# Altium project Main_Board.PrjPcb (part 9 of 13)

## Sheet Ext_GPIO_Bank2.SchDoc
size A3
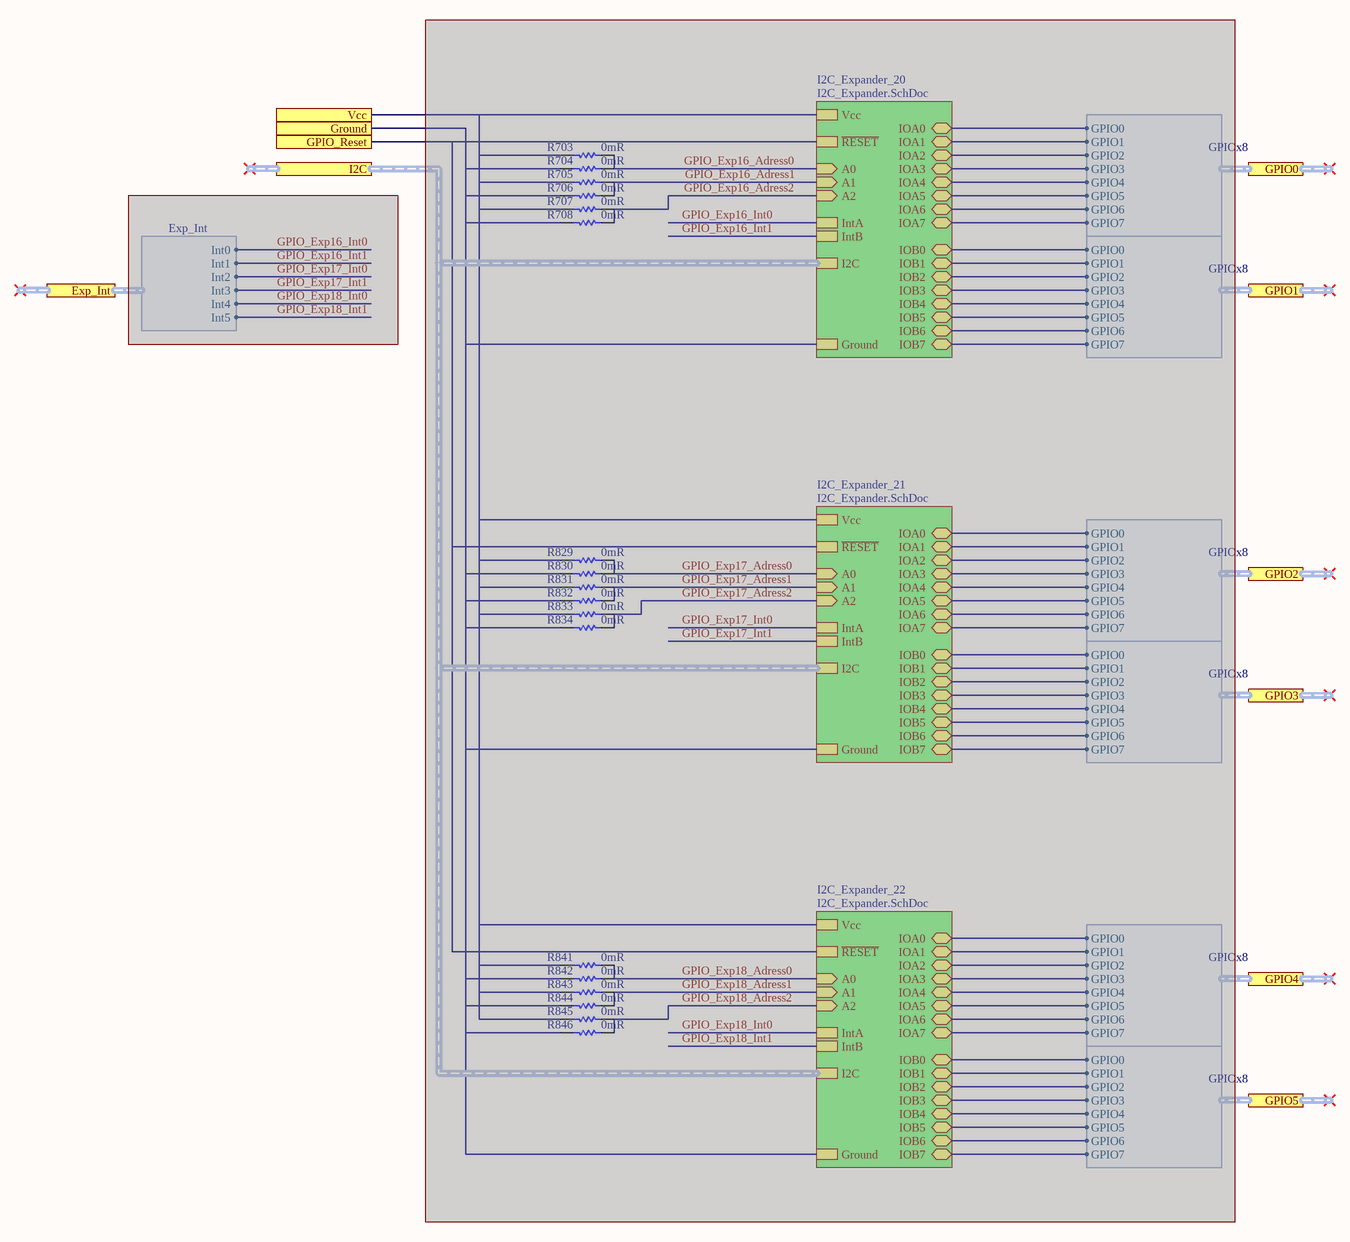
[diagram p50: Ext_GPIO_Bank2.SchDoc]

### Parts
(Parts that share a designator on the sheet are numbered #1, #2 ... from top to bottom, then left to right.)
R703#1  0mR  [RES 0402/1005 RF KK]  (masked out: inside a compile mask, not in the netlist)
R704#1  0mR  [RES 0402/1005 RF KK]  (masked out: inside a compile mask, not in the netlist)
R705#1  0mR  [RES 0402/1005 RF KK]  (masked out: inside a compile mask, not in the netlist)
R706#1  0mR  [RES 0402/1005 RF KK]  (masked out: inside a compile mask, not in the netlist)
R707#1  0mR  [RES 0402/1005 RF KK]  (masked out: inside a compile mask, not in the netlist)
R708#1  0mR  [RES 0402/1005 RF KK]  (masked out: inside a compile mask, not in the netlist)
R829#1  0mR  [RES 0402/1005 RF KK]  (masked out: inside a compile mask, not in the netlist)
R830#1  0mR  [RES 0402/1005 RF KK]  (masked out: inside a compile mask, not in the netlist)
R831#1  0mR  [RES 0402/1005 RF KK]  (masked out: inside a compile mask, not in the netlist)
R832#1  0mR  [RES 0402/1005 RF KK]  (masked out: inside a compile mask, not in the netlist)
R833#1  0mR  [RES 0402/1005 RF KK]  (masked out: inside a compile mask, not in the netlist)
R834#1  0mR  [RES 0402/1005 RF KK]  (masked out: inside a compile mask, not in the netlist)
R841#1  0mR  [RES 0402/1005 RF KK]  (masked out: inside a compile mask, not in the netlist)
R842#1  0mR  [RES 0402/1005 RF KK]  (masked out: inside a compile mask, not in the netlist)
R843#1  0mR  [RES 0402/1005 RF KK]  (masked out: inside a compile mask, not in the netlist)
R844#1  0mR  [RES 0402/1005 RF KK]  (masked out: inside a compile mask, not in the netlist)
R845#1  0mR  [RES 0402/1005 RF KK]  (masked out: inside a compile mask, not in the netlist)
R846#2  0mR  [RES 0402/1005 RF KK]  (masked out: inside a compile mask, not in the netlist)

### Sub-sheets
I2C_Expander_20 = I2C_Expander.SchDoc (masked out): IOA7 (bidir), IOA3 (bidir), IOA6 (bidir), IOA1 (bidir), IOA0 (bidir), IOA5 (bidir), IOB1 (bidir), IOB2 (bidir), IOB5 (bidir), IOB6 (bidir), IOB7 (bidir), IntA, IntB, Ground, IOB4 (bidir), IOB3 (bidir), IOA2 (bidir), IOA4 (bidir), IOB0 (bidir), Vcc, ~{RESET}, I2C (harness I2C), A2 (in), A1 (in), A0 (in)
I2C_Expander_21 = I2C_Expander.SchDoc (masked out): IOA7 (bidir), IOA3 (bidir), IOA6 (bidir), IOA1 (bidir), IOA0 (bidir), IOA5 (bidir), IOB1 (bidir), IOB2 (bidir), IOB5 (bidir), IOB6 (bidir), IOB7 (bidir), IntA, IntB, Ground, IOB4 (bidir), IOB3 (bidir), IOA2 (bidir), IOA4 (bidir), IOB0 (bidir), Vcc, ~{RESET}, I2C (harness I2C), A2 (in), A1 (in), A0 (in)
I2C_Expander_22 = I2C_Expander.SchDoc (masked out): IOA7 (bidir), IOA3 (bidir), IOA6 (bidir), IOA1 (bidir), IOA0 (bidir), IOA5 (bidir), IOB1 (bidir), IOB2 (bidir), IOB5 (bidir), IOB6 (bidir), IOB7 (bidir), IntA, IntB, Ground, IOB4 (bidir), IOB3 (bidir), IOA2 (bidir), IOA4 (bidir), IOB0 (bidir), Vcc, ~{RESET}, I2C (harness I2C), A2 (in), A1 (in), A0 (in)

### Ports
Exp_Int (harness Exp_Int), GPIO0 (harness GPIOx8), GPIO1 (harness GPIOx8), GPIO2 (harness GPIOx8), GPIO3 (harness GPIOx8), GPIO4 (harness GPIOx8), GPIO5 (harness GPIOx8), GPIO_Reset, Ground, I2C (harness I2C), Vcc

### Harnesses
GPIOx8: GPIO0, GPIO1, GPIO2, GPIO3, GPIO4, GPIO5, GPIO6, GPIO7
Exp_Int: Int0, Int1, Int2, Int3, Int4, Int5

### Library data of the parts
R703#1 R704#1 R705#1 R706#1 R707#1 R708#1 R829#1 R830#1 R831#1 R832#1 R833#1 R834#1 R841#1 R842#1 R843#1 R844#1 R845#1 R846#2 = Resistor: Manufacturer 1: Yageo; Manufacturer Part Number 1: RC0402JR-070RL; Power Rating: 62.5mW; Tolerance: 5%; Voltage Rating: 50V; Max Power Dissipation: 63mW; Temperature Coefficient: 200ppm/°C

## Sheet SFP_Group.SchDoc: SFP_Group
size A3
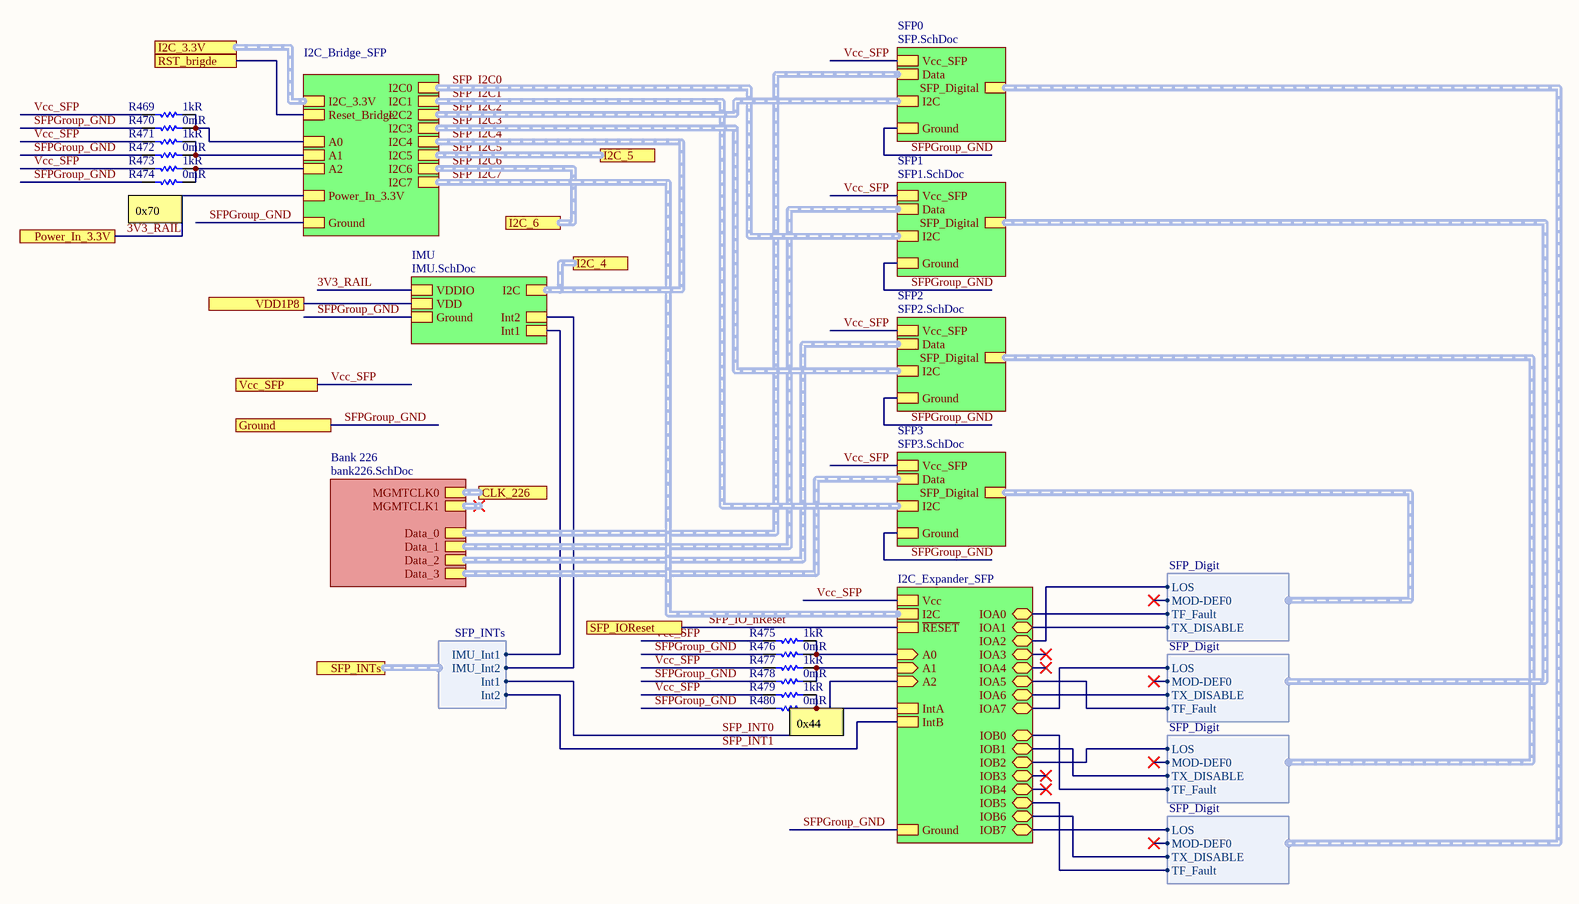
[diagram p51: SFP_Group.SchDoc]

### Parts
R469  1kR  [RES 0402/1005 RF KK]
R470  0mR  [RES 0402/1005 RF KK]
R471  1kR  [RES 0402/1005 RF KK]
R472  0mR  [RES 0402/1005 RF KK]
R473  1kR  [RES 0402/1005 RF KK]
R474  0mR  [RES 0402/1005 RF KK]
R475  1kR  [RES 0402/1005 RF KK]
R476  0mR  [RES 0402/1005 RF KK]
R477  1kR  [RES 0402/1005 RF KK]
R478  0mR  [RES 0402/1005 RF KK]
R479  1kR  [RES 0402/1005 RF KK]
R480  0mR  [RES 0402/1005 RF KK]

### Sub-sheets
Bank 226 = bank226.SchDoc: MGMTCLK0 (harness Diff_1Pair), MGMTCLK1 (harness Diff_1Pair), Data_3 (harness Diff_2PairData), Data_2 (harness Diff_2PairData), Data_1 (harness Diff_2PairData), Data_0 (harness Diff_2PairData)
I2C_Bridge_SFP = I2C_Bridge.SchDoc: I2C0 (harness I2C), I2C1 (harness I2C), I2C2 (harness I2C), I2C3 (harness I2C), I2C4 (harness I2C), I2C5 (harness I2C), I2C6 (harness I2C), I2C7 (harness I2C), A2, A1, A0, Ground, I2C_3.3V (harness I2C), Reset_Bridge, Power_In_3.3V
I2C_Expander_SFP = I2C_Expander.SchDoc: IOA7 (bidir), IOA3 (bidir), IOA6 (bidir), IOA1 (bidir), IOA0 (bidir), IOA5 (bidir), IOB1 (bidir), IOB2 (bidir), IOB5 (bidir), IOB6 (bidir), IOB7 (bidir), IntA, IntB, Ground, IOB4 (bidir), IOB3 (bidir), IOA2 (bidir), IOA4 (bidir), IOB0 (bidir), Vcc, ~{RESET}, I2C (harness I2C), A2 (in), A1 (in), A0 (in)
IMU = IMU.SchDoc: Ground, I2C (harness I2C), VDDIO, VDD, Int1, Int2
SFP0 = SFP.SchDoc: I2C (harness I2C), Vcc_SFP, SFP_Digital (harness SFP_Digit), Data (harness Diff_2PairData), Ground
SFP1 = SFP1.SchDoc: I2C (harness I2C), Vcc_SFP, SFP_Digital (harness SFP_Digit), Data (harness Diff_2PairData), Ground
SFP2 = SFP2.SchDoc: I2C (harness I2C), Vcc_SFP, SFP_Digital (harness SFP_Digit), Data (harness Diff_2PairData), Ground
SFP3 = SFP3.SchDoc: I2C (harness I2C), Vcc_SFP, SFP_Digital (harness SFP_Digit), Data (harness Diff_2PairData), Ground

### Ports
CLK_226 (harness Diff_1Pair), Ground, I2C_3.3V (harness I2C), I2C_4 (harness I2C), I2C_5 (harness I2C), I2C_6 (harness I2C), Power_In_3.3V, RST_brigde, SFP_INTs (harness SFP_INTs), SFP_IOReset, Vcc_SFP, VDD1P8

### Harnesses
SFP_Digit: LOS, MOD-DEF0, TF_Fault, TX_DISABLE
SFP_INTs: IMU_Int1, Int1, Int2, IMU_Int2

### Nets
SFPGroup_GND: R470.2 R472.2 R474.2 R476.2 R478.2 R480.2 ; port Ground, sheet SFP0/Ground, sheet SFP1/Ground, sheet SFP2/Ground, sheet SFP3/Ground, sheet I2C_Bridge_SFP/Ground, sheet IMU/Ground, sheet I2C_Expander_SFP/Ground  [project net B503_Ground]
1V8@1.5A: port VDD1P8, sheet IMU/VDD
3V3_RAIL: R469.1 R471.1 R473.1 R475.1 R477.1 R479.1 ; port Vcc_SFP, port Power_In_3.3V, sheet SFP0/Vcc_SFP, sheet SFP1/Vcc_SFP, sheet SFP2/Vcc_SFP, sheet SFP3/Vcc_SFP, sheet I2C_Bridge_SFP/Power_In_3.3V, sheet IMU/VDDIO, sheet I2C_Expander_SFP/Vcc  [also labelled Vcc_SFP]
IMU_INT1: sheet IMU/Int1, port SFP_INTs.IMU_Int1
IMU_INT2: sheet IMU/Int2, port SFP_INTs.IMU_Int2
RST_brigde: port RST_brigde, sheet I2C_Bridge_SFP/Reset_Bridge
SFP0_LOS: sheet I2C_Expander_SFP/IOB7, sheet SFP0/SFP_Digital.LOS
SFP0_TxDis: sheet I2C_Expander_SFP/IOB6, sheet SFP0/SFP_Digital.TX_DISABLE
SFP0_TxF: sheet I2C_Expander_SFP/IOB5, sheet SFP0/SFP_Digital.TF_Fault
SFP1_LOS: sheet I2C_Expander_SFP/IOA7, sheet SFP1/SFP_Digital.LOS
SFP1_TxDis: sheet I2C_Expander_SFP/IOA6, sheet SFP1/SFP_Digital.TX_DISABLE
SFP1_TxF: sheet I2C_Expander_SFP/IOA5, sheet SFP1/SFP_Digital.TF_Fault
SFP2_LOS: sheet I2C_Expander_SFP/IOB2, sheet SFP2/SFP_Digital.LOS
SFP2_TxDis: sheet I2C_Expander_SFP/IOB1, sheet SFP2/SFP_Digital.TX_DISABLE
SFP2_TxF: sheet I2C_Expander_SFP/IOB0, sheet SFP2/SFP_Digital.TF_Fault
SFP3_LOS: sheet I2C_Expander_SFP/IOA2, sheet SFP3/SFP_Digital.LOS
SFP3_TxDis: sheet I2C_Expander_SFP/IOA1, sheet SFP3/SFP_Digital.TX_DISABLE
SFP3_TxF: sheet I2C_Expander_SFP/IOA0, sheet SFP3/SFP_Digital.TF_Fault
SFP_INT0: sheet I2C_Expander_SFP/IntA, port SFP_INTs.Int1
SFP_INT1: sheet I2C_Expander_SFP/IntB, port SFP_INTs.Int2
SFP_IO_nReset: port SFP_IOReset, sheet I2C_Expander_SFP/~{RESET}
NetR469_2: R469.2 R470.1 ; sheet I2C_Bridge_SFP/A0
NetR471_2: R471.2 R472.1 ; sheet I2C_Bridge_SFP/A1
NetR473_2: R473.2 R474.1 ; sheet I2C_Bridge_SFP/A2
NetR475_2: R475.2 R476.1 ; sheet I2C_Expander_SFP/A0
NetR477_2: R477.2 R478.1 ; sheet I2C_Expander_SFP/A1
NetR479_2: R479.2 R480.1 ; sheet I2C_Expander_SFP/A2

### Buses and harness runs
harness port CLK_226 = sheet Bank 226/MGMTCLK0
harness port I2C_3.3V = sheet I2C_Bridge_SFP/I2C_3.3V
harness SFP_I2C0 = sheet I2C_Bridge_SFP/I2C0 = sheet SFP1/I2C
harness SFP_I2C1 = sheet I2C_Bridge_SFP/I2C1 = sheet SFP3/I2C
harness SFP_I2C2 = sheet I2C_Bridge_SFP/I2C2 = sheet SFP0/I2C
harness SFP_I2C3 = sheet I2C_Bridge_SFP/I2C3 = sheet SFP2/I2C
harness SFP_I2C4 = port I2C_4 = sheet I2C_Bridge_SFP/I2C4 = sheet IMU/I2C
harness SFP_I2C5 = port I2C_5 = sheet I2C_Bridge_SFP/I2C5
harness SFP_I2C6 = port I2C_6 = sheet I2C_Bridge_SFP/I2C6
harness SFP_I2C7 = sheet I2C_Bridge_SFP/I2C7 = sheet I2C_Expander_SFP/I2C
harness sheet Bank 226/Data_0 = sheet SFP0/Data
harness sheet Bank 226/Data_1 = sheet SFP1/Data
harness sheet Bank 226/Data_2 = sheet SFP2/Data
harness sheet Bank 226/Data_3 = sheet SFP3/Data

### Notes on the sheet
- (near R474) 0x70
- (near R480) 0x44

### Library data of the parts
R469 R471 R473 R475 R477 R479 = Resistor: PANASONIC - ERJ-2RKF1001X - SMD Chip Resistor, 0402 [1005 Metric], 1 kohm, ERJ2R Series, 50 V, Thick Film, 100 mW; Temperature Coefficient: 100ppm/°C; Tolerance: 1%; Voltage Rating (DC): 50V; Power Rating: 100mW
R470 R472 R474 R476 R478 R480 = Resistor: as R703#1 on sheet Ext_GPIO_Bank2

## Sheet SFP.SchDoc: SFP
size A3; Organization: Altium Limited; Address1: L3, 12a Rodborough Rd; Address2: Frenchs Forest; Address3: NSW; Address4: Australia 2086
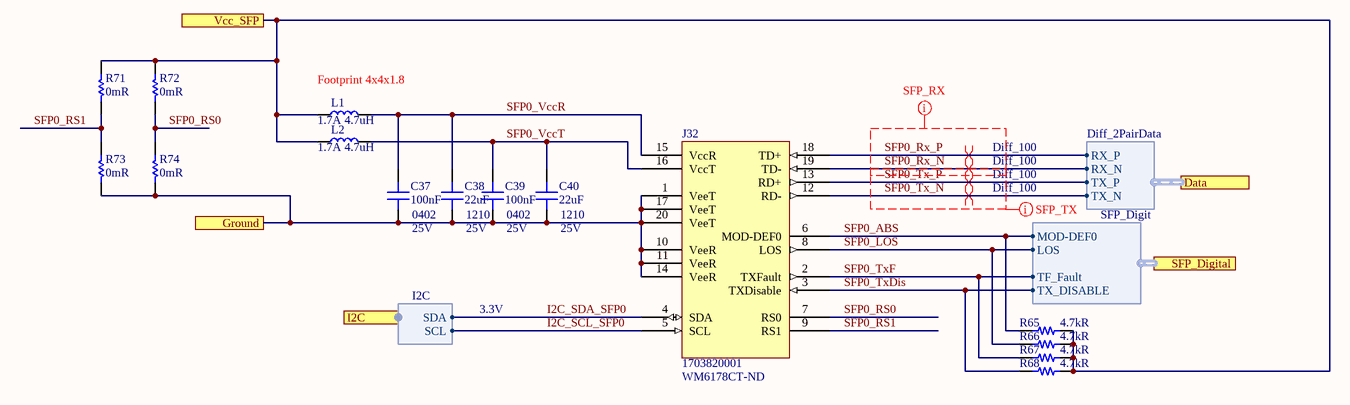
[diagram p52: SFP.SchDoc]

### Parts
C37  100nF  Case/Package: 0402  Voltage Rating: 25V  [CAP 0402/1005 KK]
C38  22uF  Case/Package: 1210  Voltage Rating: 25V  [CAP 1210/3225 - 1MM]
C39  100nF  Case/Package: 0402  Voltage Rating: 25V  [CAP 0402/1005 KK]
C40  22uF  Case/Package: 1210  Voltage Rating: 25V  [CAP 1210/3225 - 1MM]
J32  1703820001  Supplier Part Number 1: WM6178CT-ND  [1703820001]
L1  Inductance: 4.7uH  Current Rating: 1.7A  [NRS8040]  (hidden comment: NRS4018T4R7MDGJV)
L2  Inductance: 4.7uH  Current Rating: 1.7A  [NRS8040]  (hidden comment: NRS4018T4R7MDGJV)
R65  4.7kR  [RES 0402/1005 RF KK]
R66  4.7kR  [RES 0402/1005 RF KK]
R67  4.7kR  [RES 0402/1005 RF KK]
R68  4.7kR  [RES 0402/1005 RF KK]
R71  0mR  [RES 0402/1005 RF KK]
R72  0mR  [RES 0402/1005 RF KK]
R73  0mR  [RES 0402/1005 RF KK]
R74  0mR  [RES 0402/1005 RF KK]

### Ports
Data (harness Diff_2PairData), Ground, I2C (harness I2C), SFP_Digital (harness SFP_Digit), Vcc_SFP

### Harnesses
I2C: SDA, SCL
SFP_Digit: MOD-DEF0, LOS, TF_Fault, TX_DISABLE
Diff_2PairData: RX_P, RX_N, TX_P, TX_N

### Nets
B503_Ground: C37.1 C38.2 C39.1 C40.2 J32.1(VeeT) J32.10(VeeR) J32.11(VeeR) J32.14(VeeR) J32.17(VeeT) J32.20(VeeT) R73.2 R74.2 ; port Ground
3V3_RAIL: L1.1 L2.1 R65.2 R66.2 R67.2 R68.2 R71.1 R72.1 ; port Vcc_SFP
I2C_SCL_SFP0: J32.5(SCL) ; port I2C.SCL
I2C_SDA_SFP0: J32.4(SDA) ; port I2C.SDA
SFP0_ABS: J32.6(MOD-DEF0) R65.1 ; port SFP_Digital.MOD-DEF0
SFP0_LOS: J32.8(LOS) R66.1 ; port SFP_Digital.LOS
SFP0_RS0: J32.7(RS0) R72.2 R74.1
SFP0_RS1: J32.9(RS1) R71.2 R73.1
SFP0_Rx_N: J32.19(TD-) ; port Data.RX_N
SFP0_Rx_P: J32.18(TD+) ; port Data.RX_P
SFP0_Tx_N: J32.12(RD-) ; port Data.TX_N
SFP0_Tx_P: J32.13(RD+) ; port Data.TX_P
SFP0_TxDis: J32.3(TXDisable) R68.1 ; port SFP_Digital.TX_DISABLE
SFP0_TxF: J32.2(TXFault) R67.1 ; port SFP_Digital.TF_Fault
SFP0_VccR: C37.2 C38.1 J32.15(VccR) L1.2
SFP0_VccT: C39.2 C40.1 J32.16(VccT) L2.2

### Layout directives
differential pair; differential pair class Diff_100: SFP0_Rx_N, SFP0_Rx_P, SFP0_Tx_N, SFP0_Tx_P
net class SFP_RX: SFP0_Rx_N, SFP0_Rx_P
net class SFP_TX: SFP0_Rx_N, SFP0_Tx_N, SFP0_Tx_P

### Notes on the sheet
- (near L1) Footprint 4x4x1.8
- 3.3V

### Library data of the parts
C37 C39 = Capacitor: Manufacturer: Murata; Manufacturer Part Number: GRM155R71E104KE14J; Tolerance: 10%; Dielectric: X7R
C38 C40 = Capacitor: Manufacturer: Samsung; Manufacturer Part Number: CL32A226KAJNNNE; Material: Ceramic; Tolerance: 10%; Dielectric: X5R
J32 = 1703820001: Conn zSFP+ F 20 POS 0.8mm Solder RA SMD 20 Terminal 1 Port zSFP+™ Reel; Manufacturer: Molex; Number of Circuits: 20; Connector Type: Receptacle; Number of Ports: 1; Max Voltage Rating (AC): 120V; Gender: Female; Current Rating: 500mA
L1 L2 = NRS4018T4R7MDGJV: Ind Power Shielded Wirewound 4.7uH 20% 100KHz Ferrite 1.7A Embossed T/R; Manufacturer: Taiyo Yuden; Saturation Current: 2A; DC Resistance (DCR): 84mR; Self Resonant Frequency: 35MHz
R65-R68 = Resistor: Manufacturer: Panasonic; Manufacturer Part Number: ERJ-2RKF4701X; Tolerance: 1%; Temperature Coefficient: 100ppm/°C; Power Rating: 100mW; Voltage Rating: 50V
R71-R74 = Resistor: as R703#1 on sheet Ext_GPIO_Bank2

## Sheet SFP1.SchDoc: SFP1
size A3; Organization: Altium Limited; Address1: L3, 12a Rodborough Rd; Address2: Frenchs Forest; Address3: NSW; Address4: Australia 2086
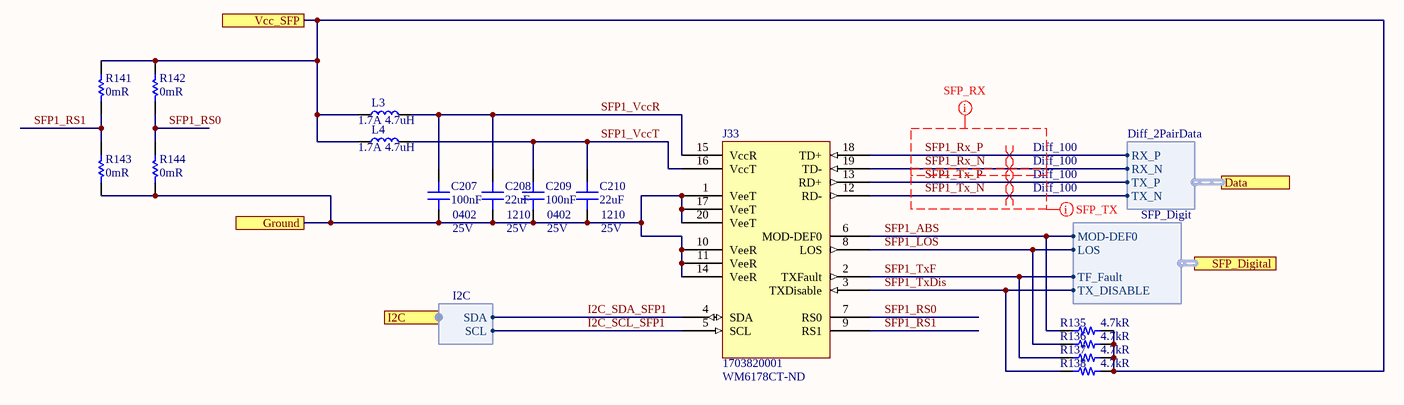
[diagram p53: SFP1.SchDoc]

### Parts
C207  100nF  Case/Package: 0402  Voltage Rating: 25V  [CAP 0402/1005 KK]
C208  22uF  Case/Package: 1210  Voltage Rating: 25V  [CAP 1210/3225 - 1MM]
C209  100nF  Case/Package: 0402  Voltage Rating: 25V  [CAP 0402/1005 KK]
C210  22uF  Case/Package: 1210  Voltage Rating: 25V  [CAP 1210/3225 - 1MM]
J33  1703820001  Supplier Part Number 1: WM6178CT-ND  [1703820001]
L3  Inductance: 4.7uH  Current Rating: 1.7A  [NRS8040]  (hidden comment: NRS4018T4R7MDGJV)
L4  Inductance: 4.7uH  Current Rating: 1.7A  [NRS8040]  (hidden comment: NRS4018T4R7MDGJV)
R135  4.7kR  [RES 0402/1005 RF KK]
R136  4.7kR  [RES 0402/1005 RF KK]
R137  4.7kR  [RES 0402/1005 RF KK]
R138  4.7kR  [RES 0402/1005 RF KK]
R141  0mR  [RES 0402/1005 RF KK]
R142  0mR  [RES 0402/1005 RF KK]
R143  0mR  [RES 0402/1005 RF KK]
R144  0mR  [RES 0402/1005 RF KK]

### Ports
Data (harness Diff_2PairData), Ground, I2C (harness I2C), SFP_Digital (harness SFP_Digit), Vcc_SFP

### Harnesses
I2C: SDA, SCL
SFP_Digit: MOD-DEF0, LOS, TF_Fault, TX_DISABLE
Diff_2PairData: RX_P, RX_N, TX_P, TX_N

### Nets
B503_Ground: C207.1 C208.2 C209.1 C210.2 J33.1(VeeT) J33.10(VeeR) J33.11(VeeR) J33.14(VeeR) J33.17(VeeT) J33.20(VeeT) R143.2 R144.2 ; port Ground
3V3_RAIL: L3.1 L4.1 R135.2 R136.2 R137.2 R138.2 R141.1 R142.1 ; port Vcc_SFP
I2C_SCL_SFP1: J33.5(SCL) ; port I2C.SCL
I2C_SDA_SFP1: J33.4(SDA) ; port I2C.SDA
SFP1_ABS: J33.6(MOD-DEF0) R135.1 ; port SFP_Digital.MOD-DEF0
SFP1_LOS: J33.8(LOS) R136.1 ; port SFP_Digital.LOS
SFP1_RS0: J33.7(RS0) R142.2 R144.1
SFP1_RS1: J33.9(RS1) R141.2 R143.1
SFP1_Rx_N: J33.19(TD-) ; port Data.RX_N
SFP1_Rx_P: J33.18(TD+) ; port Data.RX_P
SFP1_Tx_N: J33.12(RD-) ; port Data.TX_N
SFP1_Tx_P: J33.13(RD+) ; port Data.TX_P
SFP1_TxDis: J33.3(TXDisable) R138.1 ; port SFP_Digital.TX_DISABLE
SFP1_TxF: J33.2(TXFault) R137.1 ; port SFP_Digital.TF_Fault
SFP1_VccR: C207.2 C208.1 J33.15(VccR) L3.2
SFP1_VccT: C209.2 C210.1 J33.16(VccT) L4.2

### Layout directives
differential pair; differential pair class Diff_100: SFP1_Rx_N, SFP1_Rx_P, SFP1_Tx_N, SFP1_Tx_P
net class SFP_RX: SFP1_Rx_N, SFP1_Rx_P
net class SFP_TX: SFP1_Rx_N, SFP1_Tx_N, SFP1_Tx_P

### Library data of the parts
C207 C209 = Capacitor: as C37 on sheet SFP
C208 C210 = Capacitor: as C38 on sheet SFP
J33 = 1703820001: as J32 on sheet SFP
L3 L4 = NRS4018T4R7MDGJV: as L1 on sheet SFP
R135-R138 = Resistor: as R65-R68 on sheet SFP
R141-R144 = Resistor: as R703#1 on sheet Ext_GPIO_Bank2

## Sheet SFP2.SchDoc: SFP2
size A3; Organization: Altium Limited; Address1: L3, 12a Rodborough Rd; Address2: Frenchs Forest; Address3: NSW; Address4: Australia 2086
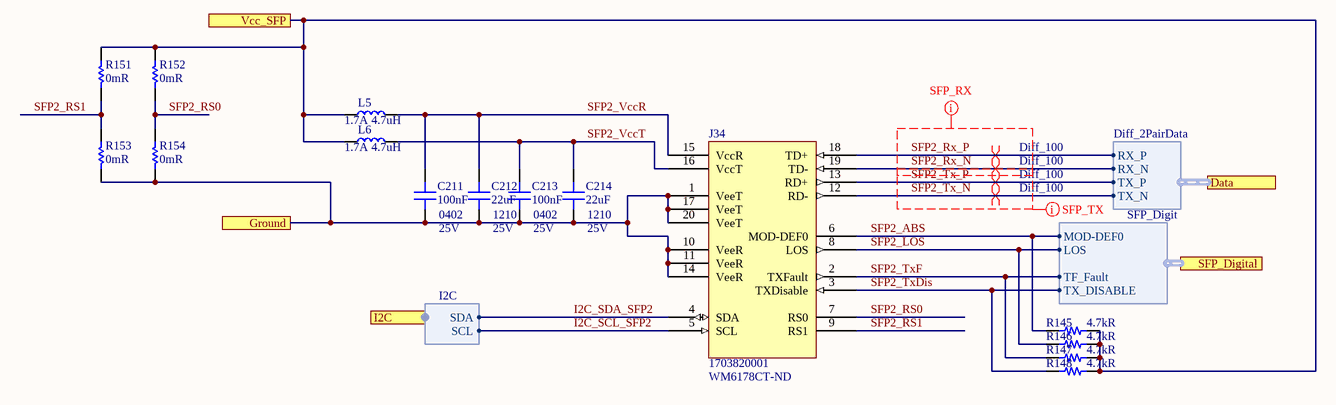
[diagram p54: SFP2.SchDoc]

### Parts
C211  100nF  Case/Package: 0402  Voltage Rating: 25V  [CAP 0402/1005 KK]
C212  22uF  Case/Package: 1210  Voltage Rating: 25V  [CAP 1210/3225 - 1MM]
C213  100nF  Case/Package: 0402  Voltage Rating: 25V  [CAP 0402/1005 KK]
C214  22uF  Case/Package: 1210  Voltage Rating: 25V  [CAP 1210/3225 - 1MM]
J34  1703820001  Supplier Part Number 1: WM6178CT-ND  [1703820001]
L5  Inductance: 4.7uH  Current Rating: 1.7A  [NRS8040]  (hidden comment: NRS4018T4R7MDGJV)
L6  Inductance: 4.7uH  Current Rating: 1.7A  [NRS8040]  (hidden comment: NRS4018T4R7MDGJV)
R145  4.7kR  [RES 0402/1005 RF KK]
R146  4.7kR  [RES 0402/1005 RF KK]
R147  4.7kR  [RES 0402/1005 RF KK]
R148  4.7kR  [RES 0402/1005 RF KK]
R151  0mR  [RES 0402/1005 RF KK]
R152  0mR  [RES 0402/1005 RF KK]
R153  0mR  [RES 0402/1005 RF KK]
R154  0mR  [RES 0402/1005 RF KK]

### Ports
Data (harness Diff_2PairData), Ground, I2C (harness I2C), SFP_Digital (harness SFP_Digit), Vcc_SFP

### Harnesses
I2C: SDA, SCL
SFP_Digit: MOD-DEF0, LOS, TF_Fault, TX_DISABLE
Diff_2PairData: RX_P, RX_N, TX_P, TX_N

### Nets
B503_Ground: C211.1 C212.2 C213.1 C214.2 J34.1(VeeT) J34.10(VeeR) J34.11(VeeR) J34.14(VeeR) J34.17(VeeT) J34.20(VeeT) R153.2 R154.2 ; port Ground
3V3_RAIL: L5.1 L6.1 R145.2 R146.2 R147.2 R148.2 R151.1 R152.1 ; port Vcc_SFP
I2C_SCL_SFP2: J34.5(SCL) ; port I2C.SCL
I2C_SDA_SFP2: J34.4(SDA) ; port I2C.SDA
SFP2_ABS: J34.6(MOD-DEF0) R145.1 ; port SFP_Digital.MOD-DEF0
SFP2_LOS: J34.8(LOS) R146.1 ; port SFP_Digital.LOS
SFP2_RS0: J34.7(RS0) R152.2 R154.1
SFP2_RS1: J34.9(RS1) R151.2 R153.1
SFP2_Rx_N: J34.19(TD-) ; port Data.RX_N
SFP2_Rx_P: J34.18(TD+) ; port Data.RX_P
SFP2_Tx_N: J34.12(RD-) ; port Data.TX_N
SFP2_Tx_P: J34.13(RD+) ; port Data.TX_P
SFP2_TxDis: J34.3(TXDisable) R148.1 ; port SFP_Digital.TX_DISABLE
SFP2_TxF: J34.2(TXFault) R147.1 ; port SFP_Digital.TF_Fault
SFP2_VccR: C211.2 C212.1 J34.15(VccR) L5.2
SFP2_VccT: C213.2 C214.1 J34.16(VccT) L6.2

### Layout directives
differential pair; differential pair class Diff_100: SFP2_Rx_N, SFP2_Rx_P, SFP2_Tx_N, SFP2_Tx_P
net class SFP_RX: SFP2_Rx_N, SFP2_Rx_P
net class SFP_TX: SFP2_Rx_N, SFP2_Tx_N, SFP2_Tx_P

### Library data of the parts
C211 C213 = Capacitor: as C37 on sheet SFP
C212 C214 = Capacitor: as C38 on sheet SFP
J34 = 1703820001: as J32 on sheet SFP
L5 L6 = NRS4018T4R7MDGJV: as L1 on sheet SFP
R145-R148 = Resistor: as R65-R68 on sheet SFP
R151-R154 = Resistor: as R703#1 on sheet Ext_GPIO_Bank2

## Sheet SFP3.SchDoc: SFP3
size A3; Organization: Altium Limited; Address1: L3, 12a Rodborough Rd; Address2: Frenchs Forest; Address3: NSW; Address4: Australia 2086
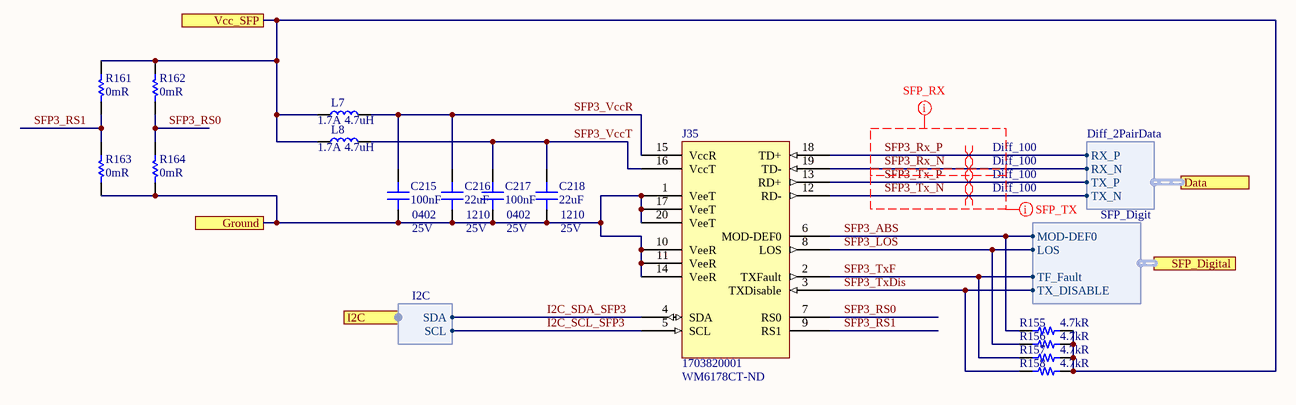
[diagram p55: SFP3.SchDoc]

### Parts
C215  100nF  Case/Package: 0402  Voltage Rating: 25V  [CAP 0402/1005 KK]
C216  22uF  Case/Package: 1210  Voltage Rating: 25V  [CAP 1210/3225 - 1MM]
C217  100nF  Case/Package: 0402  Voltage Rating: 25V  [CAP 0402/1005 KK]
C218  22uF  Case/Package: 1210  Voltage Rating: 25V  [CAP 1210/3225 - 1MM]
J35  1703820001  Supplier Part Number 1: WM6178CT-ND  [1703820001]
L7  Inductance: 4.7uH  Current Rating: 1.7A  [NRS8040]  (hidden comment: NRS4018T4R7MDGJV)
L8  Inductance: 4.7uH  Current Rating: 1.7A  [NRS8040]  (hidden comment: NRS4018T4R7MDGJV)
R155  4.7kR  [RES 0402/1005 RF KK]
R156  4.7kR  [RES 0402/1005 RF KK]
R157  4.7kR  [RES 0402/1005 RF KK]
R158  4.7kR  [RES 0402/1005 RF KK]
R161  0mR  [RES 0402/1005 RF KK]
R162  0mR  [RES 0402/1005 RF KK]
R163  0mR  [RES 0402/1005 RF KK]
R164  0mR  [RES 0402/1005 RF KK]

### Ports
Data (harness Diff_2PairData), Ground, I2C (harness I2C), SFP_Digital (harness SFP_Digit), Vcc_SFP

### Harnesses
I2C: SDA, SCL
SFP_Digit: MOD-DEF0, LOS, TF_Fault, TX_DISABLE
Diff_2PairData: RX_P, RX_N, TX_P, TX_N

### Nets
B503_Ground: C215.1 C216.2 C217.1 C218.2 J35.1(VeeT) J35.10(VeeR) J35.11(VeeR) J35.14(VeeR) J35.17(VeeT) J35.20(VeeT) R163.2 R164.2 ; port Ground
3V3_RAIL: L7.1 L8.1 R155.2 R156.2 R157.2 R158.2 R161.1 R162.1 ; port Vcc_SFP
I2C_SCL_SFP3: J35.5(SCL) ; port I2C.SCL
I2C_SDA_SFP3: J35.4(SDA) ; port I2C.SDA
SFP3_ABS: J35.6(MOD-DEF0) R155.1 ; port SFP_Digital.MOD-DEF0
SFP3_LOS: J35.8(LOS) R156.1 ; port SFP_Digital.LOS
SFP3_RS0: J35.7(RS0) R162.2 R164.1
SFP3_RS1: J35.9(RS1) R161.2 R163.1
SFP3_Rx_N: J35.19(TD-) ; port Data.RX_N
SFP3_Rx_P: J35.18(TD+) ; port Data.RX_P
SFP3_Tx_N: J35.12(RD-) ; port Data.TX_N
SFP3_Tx_P: J35.13(RD+) ; port Data.TX_P
SFP3_TxDis: J35.3(TXDisable) R158.1 ; port SFP_Digital.TX_DISABLE
SFP3_TxF: J35.2(TXFault) R157.1 ; port SFP_Digital.TF_Fault
SFP3_VccR: C215.2 C216.1 J35.15(VccR) L7.2
SFP3_VccT: C217.2 C218.1 J35.16(VccT) L8.2

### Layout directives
differential pair; differential pair class Diff_100: SFP3_Rx_N, SFP3_Rx_P, SFP3_Tx_N, SFP3_Tx_P
net class SFP_RX: SFP3_Rx_N, SFP3_Rx_P
net class SFP_TX: SFP3_Rx_N, SFP3_Tx_N, SFP3_Tx_P

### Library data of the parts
C215 C217 = Capacitor: as C37 on sheet SFP
C216 C218 = Capacitor: as C38 on sheet SFP
J35 = 1703820001: as J32 on sheet SFP
L7 L8 = NRS4018T4R7MDGJV: as L1 on sheet SFP
R155-R158 = Resistor: as R65-R68 on sheet SFP
R161-R164 = Resistor: as R703#1 on sheet Ext_GPIO_Bank2

## Sheet bank226.SchDoc: Bank226
size A3; Organization: Altium Limited; Address1: L3, 12a Rodborough Rd; Address2: Frenchs Forest; Address3: NSW; Address4: Australia 2086
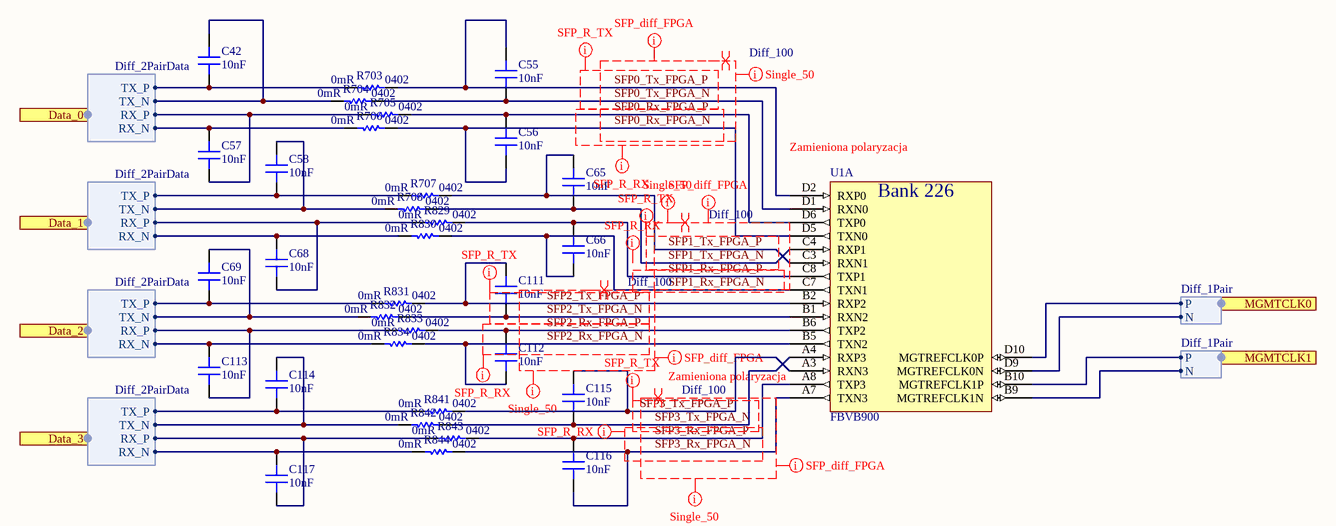
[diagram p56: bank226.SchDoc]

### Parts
(Parts that share a designator on the sheet are numbered #1, #2 ... from top to bottom, then left to right.)
C42  10nF  [CAP 0402/1005 KK]
C55#2  10nF  [CAP 0402/1005 KK]
C56#2  10nF  [CAP 0402/1005 KK]
C57#2  10nF  [CAP 0402/1005 KK]
C58#2  10nF  [CAP 0402/1005 KK]
C65#2  10nF  [CAP 0402/1005 KK]
C66#2  10nF  [CAP 0402/1005 KK]
C68#2  10nF  [CAP 0402/1005 KK]
C69#2  10nF  [CAP 0402/1005 KK]
C111#2  10nF  [CAP 0402/1005 KK]
C112#2  10nF  [CAP 0402/1005 KK]
C113#2  10nF  [CAP 0402/1005 KK]
C114#2  10nF  [CAP 0402/1005 KK]
C115#2  10nF  [CAP 0402/1005 KK]
C116#2  10nF  [CAP 0402/1005 KK]
C117#2  10nF  [CAP 0402/1005 KK]
R703#2  0mR  Case/Package: 0402  [RES 0402/1005 RF KK]
R704#2  0mR  Case/Package: 0402  [RES 0402/1005 RF KK]
R705#2  0mR  Case/Package: 0402  [RES 0402/1005 RF KK]
R706#2  0mR  Case/Package: 0402  [RES 0402/1005 RF KK]
R707#2  0mR  Case/Package: 0402  [RES 0402/1005 RF KK]
R708#2  0mR  Case/Package: 0402  [RES 0402/1005 RF KK]
R829#2  0mR  Case/Package: 0402  [RES 0402/1005 RF KK]
R830#2  0mR  Case/Package: 0402  [RES 0402/1005 RF KK]
R831#2  0mR  Case/Package: 0402  [RES 0402/1005 RF KK]
R832#2  0mR  Case/Package: 0402  [RES 0402/1005 RF KK]
R833#2  0mR  Case/Package: 0402  [RES 0402/1005 RF KK]
R834#2  0mR  Case/Package: 0402  [RES 0402/1005 RF KK]
R841#2  0mR  Case/Package: 0402  [RES 0402/1005 RF KK]
R842#2  0mR  Case/Package: 0402  [RES 0402/1005 RF KK]
R843#2  0mR  Case/Package: 0402  [RES 0402/1005 RF KK]
R844#2  0mR  Case/Package: 0402  [RES 0402/1005 RF KK]
U1  FBVB900  [FBVB900 XX]  (part A of 23)

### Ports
Data_0 (harness Diff_2PairData), Data_1 (harness Diff_2PairData), Data_2 (harness Diff_2PairData), Data_3 (harness Diff_2PairData), MGMTCLK0 (harness Diff_1Pair), MGMTCLK1 (harness Diff_1Pair)

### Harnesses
Diff_2PairData: RX_P, RX_N, TX_P, TX_N
Diff_1Pair: P, N

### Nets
LTC6952_1_MATCH_Out0_N: U1.D9(MGTREFCLK0N) ; port MGMTCLK0.N
LTC6952_1_MATCH_Out0_P: U1.D10(MGTREFCLK0P) ; port MGMTCLK0.P
SFP0_Rx_FPGA_N: C56#2.1 R706#2.1 U1.D5(TXN0)
SFP0_Rx_FPGA_P: C56#2.2 R705#2.1 U1.D6(TXP0)
SFP0_Rx_N: C57#2.2 R706#2.2 ; port Data_0.RX_N
SFP0_Rx_P: C57#2.1 R705#2.2 ; port Data_0.RX_P
SFP0_Tx_FPGA_N: C55#2.1 R704#2.1 U1.D1(RXN0)
SFP0_Tx_FPGA_P: C55#2.2 R703#2.1 U1.D2(RXP0)
SFP0_Tx_N: C42.2 R704#2.2 ; port Data_0.TX_N
SFP0_Tx_P: C42.1 R703#2.2 ; port Data_0.TX_P
SFP1_Rx_FPGA_N: C66#2.1 R830#2.1 U1.C7(TXN1)
SFP1_Rx_FPGA_P: C66#2.2 R829#2.1 U1.C8(TXP1)
SFP1_Rx_N: C68#2.2 R830#2.2 ; port Data_1.RX_N
SFP1_Rx_P: C68#2.1 R829#2.2 ; port Data_1.RX_P
SFP1_Tx_FPGA_N: C65#2.1 R708#2.1 U1.C4(RXP1)
SFP1_Tx_FPGA_P: C65#2.2 R707#2.1 U1.C3(RXN1)
SFP1_Tx_N: C58#2.2 R708#2.2 ; port Data_1.TX_N
SFP1_Tx_P: C58#2.1 R707#2.2 ; port Data_1.TX_P
SFP2_Rx_FPGA_N: C112#2.1 R834#2.1 U1.B5(TXN2)
SFP2_Rx_FPGA_P: C112#2.2 R833#2.1 U1.B6(TXP2)
SFP2_Rx_N: C113#2.2 R834#2.2 ; port Data_2.RX_N
SFP2_Rx_P: C113#2.1 R833#2.2 ; port Data_2.RX_P
SFP2_Tx_FPGA_N: C111#2.1 R832#2.1 U1.B1(RXN2)
SFP2_Tx_FPGA_P: C111#2.2 R831#2.1 U1.B2(RXP2)
SFP2_Tx_N: C69#2.2 R832#2.2 ; port Data_2.TX_N
SFP2_Tx_P: C69#2.1 R831#2.2 ; port Data_2.TX_P
SFP3_Rx_FPGA_N: C116#2.1 R844#2.1 U1.A7(TXN3)
SFP3_Rx_FPGA_P: C116#2.2 R843#2.1 U1.A8(TXP3)
SFP3_Rx_N: C117#2.2 R844#2.2 ; port Data_3.RX_N
SFP3_Rx_P: C117#2.1 R843#2.2 ; port Data_3.RX_P
SFP3_Tx_FPGA_N: C115#2.1 R842#2.1 U1.A4(RXP3)
SFP3_Tx_FPGA_P: C115#2.2 R841#2.1 U1.A3(RXN3)
SFP3_Tx_N: C114#2.2 R842#2.2 ; port Data_3.TX_N
SFP3_Tx_P: C114#2.1 R841#2.2 ; port Data_3.TX_P
NetU1_B9: U1.B9(MGTREFCLK1N) ; port MGMTCLK1.N
NetU1_B10: U1.B10(MGTREFCLK1P) ; port MGMTCLK1.P

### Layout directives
differential pair; differential pair class Diff_100: SFP0_Rx_FPGA_N, SFP0_Rx_FPGA_P, SFP0_Tx_FPGA_N, SFP0_Tx_FPGA_P, SFP1_Rx_FPGA_N, SFP1_Rx_FPGA_P, SFP1_Tx_FPGA_N, SFP1_Tx_FPGA_P, SFP2_Rx_FPGA_N, SFP2_Rx_FPGA_P, SFP2_Tx_FPGA_N, SFP2_Tx_FPGA_P, SFP3_Rx_FPGA_N, SFP3_Rx_FPGA_P, SFP3_Tx_FPGA_N
net class SFP_diff_FPGA: SFP0_Rx_FPGA_N, SFP0_Rx_FPGA_P, SFP0_Tx_FPGA_N, SFP0_Tx_FPGA_P, SFP1_Rx_FPGA_N, SFP1_Rx_FPGA_P, SFP1_Tx_FPGA_N, SFP1_Tx_FPGA_P, SFP2_Rx_FPGA_N, SFP2_Rx_FPGA_P, SFP2_Tx_FPGA_N, SFP2_Tx_FPGA_P, SFP3_Rx_FPGA_N, SFP3_Rx_FPGA_P, SFP3_Tx_FPGA_N
net class Single_50: SFP0_Rx_FPGA_N, SFP0_Rx_FPGA_P, SFP0_Tx_FPGA_N, SFP0_Tx_FPGA_P, SFP1_Rx_FPGA_N, SFP1_Rx_FPGA_P, SFP1_Tx_FPGA_N, SFP1_Tx_FPGA_P, SFP2_Rx_FPGA_N, SFP2_Rx_FPGA_P, SFP2_Tx_FPGA_N, SFP2_Tx_FPGA_P, SFP3_Rx_FPGA_N, SFP3_Rx_FPGA_P, SFP3_Tx_FPGA_N
net class SFP_R_RX: (no net found under the mark), SFP0_Rx_FPGA_N, SFP0_Rx_FPGA_P, SFP2_Rx_FPGA_N, SFP2_Rx_FPGA_P, SFP3_Rx_FPGA_N, SFP3_Rx_FPGA_P
net class SFP_R_TX: SFP0_Tx_FPGA_N, SFP0_Tx_FPGA_P, SFP1_Tx_FPGA_N, SFP1_Tx_FPGA_P, SFP2_Tx_FPGA_N, SFP2_Tx_FPGA_P, SFP3_Tx_FPGA_N, SFP3_Tx_FPGA_P

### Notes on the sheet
- (near U1) Zamieniona polaryzacja

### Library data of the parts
C42 C55#2 C56#2 C57#2 C58#2 C65#2 C66#2 C68#2 C69#2 C111#2 C112#2 C113#2 C114#2 C115#2 C116#2 C117#2 = Capacitor: Manufacturer: KEMET; Manufacturer Part Number: C0402C103K4RACTU; Dielectric Material: Ceramic; Tolerance: 10%; Voltage Rating (DC): 16V; Dielectric: X7R; Dissipation Factor: 3.5%
R703#2 R704#2 R705#2 R706#2 R707#2 R708#2 R829#2 R830#2 R831#2 R832#2 R833#2 R834#2 R841#2 R842#2 R843#2 R844#2 = Resistor: as R703#1 on sheet Ext_GPIO_Bank2
U1 = FBVB900: FPGA Zynq UltraScale+ Family 192150 Cells 20nm Technology 0.85V 900-Pin FCBGA Tray; Manufacturer Part Number: XCZU4CG-1FBVB900E; Manufacturer: Xilinx; Peripherals: WDT,DMA; Interface: I2C,SPI,USB,Ethernet,MMC,SDIO,SD,UART,USART,EBI/EMI; Core Architecture: ARM; RAM Size: 256KB; Frequency: 500MHz; Number of I/Os: 204

## Sheet IMU.SchDoc: IMU
size A3
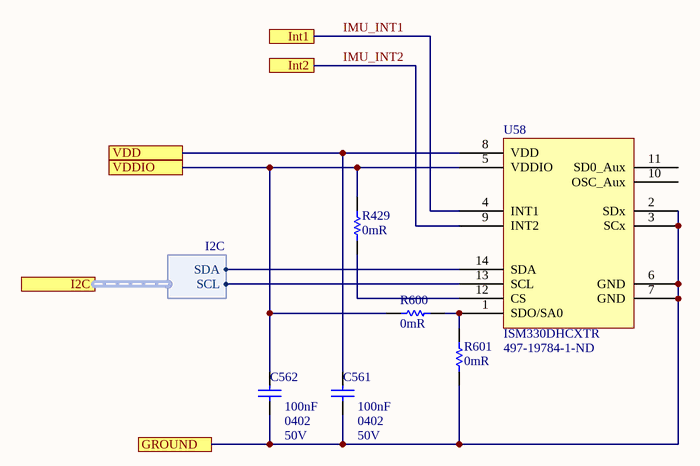
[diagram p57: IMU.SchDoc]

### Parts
C561  100nF  Case Code (Imperial): 0402  Voltage: 50V  [CAP 0402/1005 KK]
C562  100nF  Case Code (Imperial): 0402  Voltage: 50V  [CAP 0402/1005 KK]
R429  0mR  [RES 0402/1005 RF KK]
R600  0mR  [RES 0402/1005 RF KK]
R601  0mR  [RES 0402/1005 RF KK]
U58  ISM330DHCXTR  Supplier Part Number 1: 497-19784-1-ND  [ISM330DHCXL]

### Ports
GROUND, I2C (harness I2C), Int1, Int2, VDD, VDDIO

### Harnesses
I2C: SCL, SDA

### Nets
B503_Ground: C561.1 C562.1 R601.1 U58.2(SDx) U58.3(SCx) U58.6(GND) U58.7(GND) ; port GROUND
1V8@1.5A: C561.2 U58.8(VDD) ; port VDD
3V3_RAIL: C562.2 R429.2 R600.2 U58.5(VDDIO) ; port VDDIO
IMU_INT1: U58.4(INT1) ; port Int1
IMU_INT2: U58.9(INT2) ; port Int2
SFP_I2C4.SCL: U58.13(SCL) ; port I2C.SCL
SFP_I2C4.SDA: U58.14(SDA) ; port I2C.SDA
NetR429_1: R429.1 U58.12(CS)
NetR600_1: R600.1 R601.2 U58.1(SDO/SA0)

Not connected (* = marked no-connect by the designer): U58 10(OSC_Aux) 11(SD0_Aux)

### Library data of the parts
C561 C562 = Capacitor: CAP CER 0.1UF 50V X5R 0402; Manufacturer: Murata; Manufacturer Part Number: GRM155R61H104KE14D; Dielectric Material: Ceramic; Dissipation Factor: 0.025%; Tolerance: 10%
R429 R600 R601 = Resistor: Manufacturer: Yageo; Manufacturer Part Number: RC0402JR-070RL; Power Rating: 62.5mW; Tolerance: 5%; Voltage Rating: 50V; Max Power Dissipation: 63mW; Temperature Coefficient: 200ppm/°C
U58 = ISM330DHCXTR: Manufacturer 1: STMicroelectronics

## Sheet Detektor_otwarcia.SchDoc
size A3
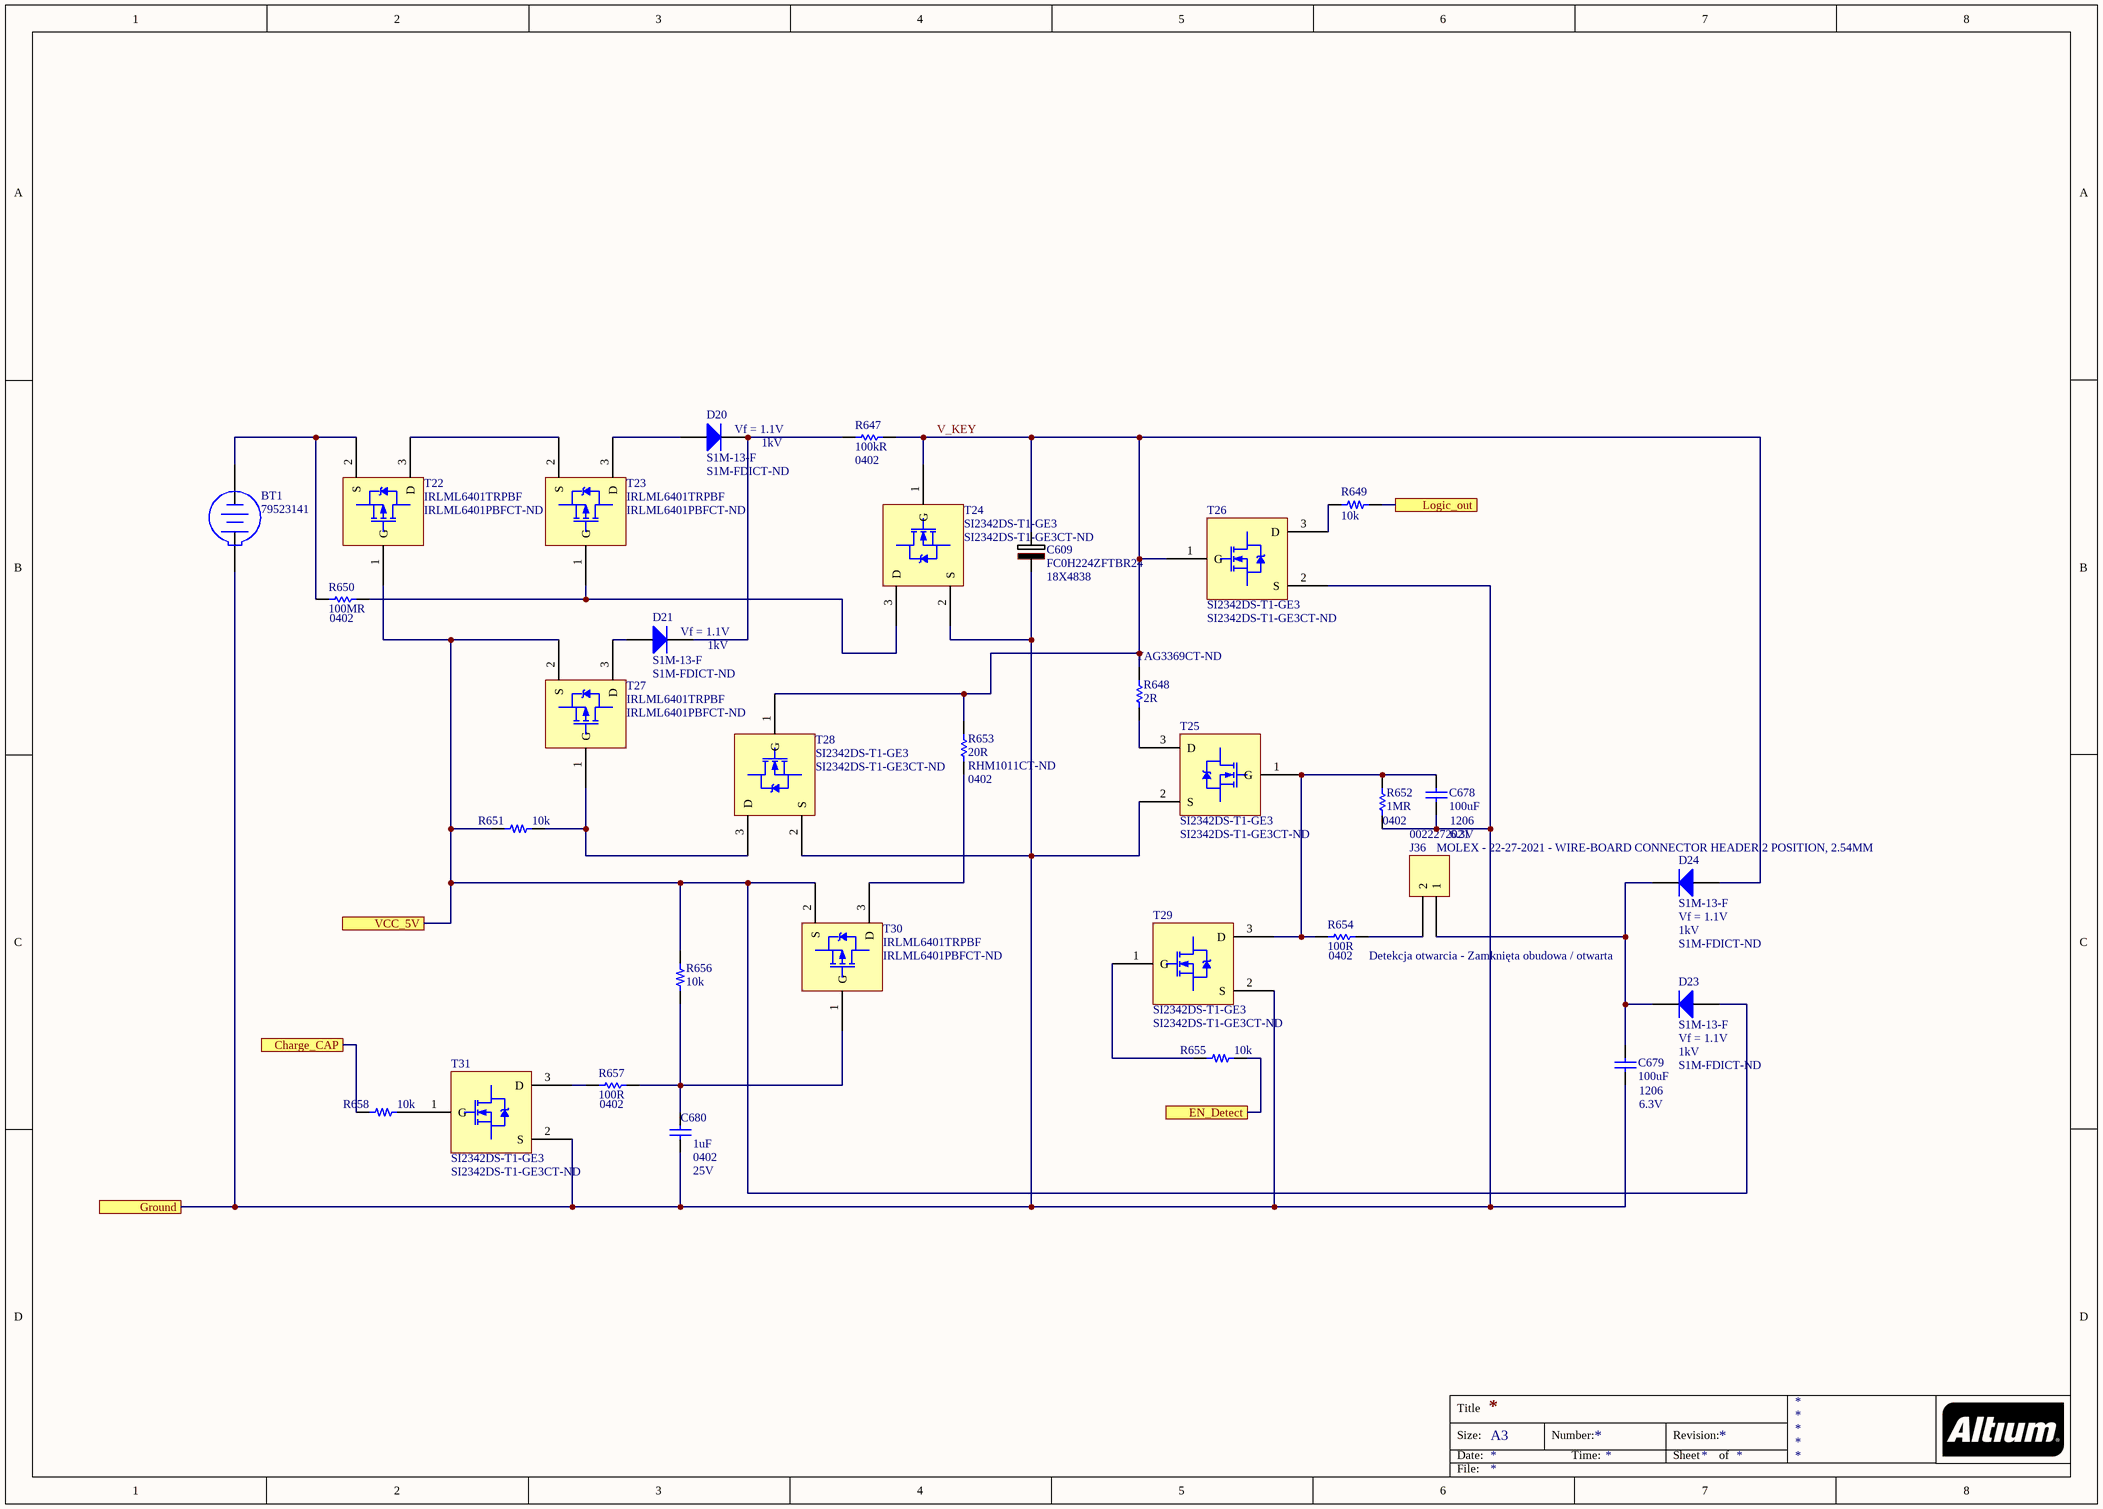
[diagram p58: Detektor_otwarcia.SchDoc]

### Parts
BT1  79523141  [79523141]
C609  FC0H224ZFTBR24  Supplier Part Number 1: 18X4838  [FC0H224ZFTBR24]
C678  100uF  Case/Package: 1206  Voltage Rating: 6.3V  [CAP 1206/3216]
C679  100uF  Case/Package: 1206  Voltage Rating: 6.3V  [CAP 1206/3216]
C680  1uF  Case/Package: 0402  Voltage Rating: 25V  [CAP 0402/1005 KK]
D20  S1M-13-F  Forward Voltage: Vf = 1.1V  Reverse Voltage (DC): 1kV  Supplier Part Number 1: S1M-FDICT-ND  [S1M-13-F]
D21  S1M-13-F  Forward Voltage: Vf = 1.1V  Reverse Voltage (DC): 1kV  Supplier Part Number 1: S1M-FDICT-ND  [S1M-13-F]
D23  S1M-13-F  Forward Voltage: Vf = 1.1V  Reverse Voltage (DC): 1kV  Supplier Part Number 1: S1M-FDICT-ND  [S1M-13-F]
D24  S1M-13-F  Forward Voltage: Vf = 1.1V  Reverse Voltage (DC): 1kV  Supplier Part Number 1: S1M-FDICT-ND  [S1M-13-F]
J36  MOLEX - 22-27-2021 - WIRE-BOARD CONNECTOR HEADER 2 POSITION, 2.54MM  Supplier Part Number 1: 0022272021  [MOLEX KK 0022272021]
R647  100kR  Case/Package: 0402  [RES 0402/1005 RF KK]
R648  2R  Supplier Part Number 1: YAG3369CT-ND  [RES 0402/1005 RF KK]
R649  10k  [RES 0402/1005 RF KK]
R650  100MR  Case/Package: 0402  [RES 0402/1005 RF KK]
R651  10k  [RES 0402/1005 RF KK]
R652  1MR  Case/Package: 0402  [RES 0402/1005 RF KK]
R653  20R  Supplier Part Number 1: RHM1011CT-ND  Case/Package: 0402  [RES 0402/1005 RF KK]
R654  100R  Case/Package: 0402  [RES 0402/1005 RF KK]
R655  10k  [RES 0402/1005 RF KK]
R656  10k  [RES 0402/1005 RF KK]
R657  100R  Case/Package: 0402  [RES 0402/1005 RF KK]
R658  10k  [RES 0402/1005 RF KK]
T22  IRLML6401TRPBF  Supplier Part Number 1: IRLML6401PBFCT-ND  [IRLML6401PbF]
T23  IRLML6401TRPBF  Supplier Part Number 1: IRLML6401PBFCT-ND  [IRLML6401PbF]
T24  SI2342DS-T1-GE3  Supplier Part Number 1: SI2342DS-T1-GE3CT-ND  [SI2342DS-T1-GE3]
T25  SI2342DS-T1-GE3  Supplier Part Number 1: SI2342DS-T1-GE3CT-ND  [SI2342DS-T1-GE3]
T26  SI2342DS-T1-GE3  Supplier Part Number 1: SI2342DS-T1-GE3CT-ND  [SI2342DS-T1-GE3]
T27  IRLML6401TRPBF  Supplier Part Number 1: IRLML6401PBFCT-ND  [IRLML6401PbF]
T28  SI2342DS-T1-GE3  Supplier Part Number 1: SI2342DS-T1-GE3CT-ND  [SI2342DS-T1-GE3]
T29  SI2342DS-T1-GE3  Supplier Part Number 1: SI2342DS-T1-GE3CT-ND  [SI2342DS-T1-GE3]
T30  IRLML6401TRPBF  Supplier Part Number 1: IRLML6401PBFCT-ND  [IRLML6401PbF]
T31  SI2342DS-T1-GE3  Supplier Part Number 1: SI2342DS-T1-GE3CT-ND  [SI2342DS-T1-GE3]

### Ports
Charge_CAP, EN_Detect, Ground, Logic_out, VCC_5V

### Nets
B503_Ground: BT1.1(+) C609.1(-) C678.1 C679.1 C680.2 R652.1 T24.2(S) T25.2(S) T26.2(S) T28.2(S) T29.2(S) T31.2(S) ; port Ground
5V_RAIL: D23.2(A) R651.2 R656.1 T22.1(G) T27.2(S) T30.2(S) ; port VCC_5V
Charge_CAP: R658.2 ; port Charge_CAP
CSU: R649.1 ; port Logic_out
EN_Detect: R655.1 ; port EN_Detect
V_KEY: C609.2(+) D24.2(A) R647.1 R648.1 R653.1 T24.1(G) T26.1(G) T28.1(G)
NetBT1_2: BT1.2(-) R650.1 T22.2(S)
NetC678_2: C678.2 R652.2 R654.1 T25.1(G) T29.3(D)
NetC679_2: C679.2 D23.1(K) D24.1(K) J36.1
NetC680_1: C680.1 R656.2 R657.2 T30.1(G)
NetD20_1: D20.1(K) D21.1(K) R647.2
NetD20_2: D20.2(A) T23.3(D)
NetD21_2: D21.2(A) T27.3(D)
NetJ36_2: J36.2 R654.2
NetR648_2: R648.2 T25.3(D)
NetR649_2: R649.2 T26.3(D)
NetR650_2: R650.2 T23.1(G) T24.3(D)
NetR651_1: R651.1 T27.1(G) T28.3(D)
NetR653_2: R653.2 T30.3(D)
NetR655_2: R655.2 T29.1(G)
NetR657_1: R657.1 T31.3(D)
NetR658_1: R658.1 T31.1(G)
NetT22_3: T22.3(D) T23.2(S)

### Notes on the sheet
- (near R654) Detekcja otwarcia - Zamknięta obudowa / otwarta

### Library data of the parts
BT1 = 79523141: WA-BCMC Battery Holder, SMT, Battery Type 2016/2020/2025/2032
C609 = FC0H224ZFTBR24: Supercapacitors / Ultracapacitors 0.22F 5.5volts SMD Super Capacitor; Manufacturer: KEMET; Capacitance: 220mF; Tolerance: 80%; Voltage Rating: 5.5V; ESR (Equivalent Series Resistance): 25R; Leakage Current: 330uA
C678 C679 = Capacitor: Cap Ceramic 100uF 6.3V X6T 20% Pad SMD 1206 105C T/R; Manufacturer: Murata; Manufacturer Part Number: GRM31CD80J107ME39L; Dissipation Factor: 0.1%
C680 = Capacitor: MURATA - GRT155R61E105KE01D - SMD Multilayer Ceramic Capacitor, 1 µF, 25 V, 0402 [1005 Metric], ± 10%, X5R, GRT Series - SMD Multilayer Ceramic Capacitor, 1 µF, 25 V, 0402 [1005 Metric], ± 10%, X5R, GRT Series
D20 D21 D23 D24 = S1M-13-F: DIODE GEN PURP 1KV 1A SMA; Manufacturer: Diodes; Recovery Time: 1.8us; Peak Reverse Current: 5uA; Reverse Recovery Time: 3us; Peak Non-Repetitive Surge Current: 30A; Polarity: Standard; Capacitance: 10pF
J36 = 2 Pin: Number of Contacts: 2; Gender: Male; Contact Resistance: 20mR; Current Rating: 4A; Voltage Rating (DC): 250V; Insulation Resistance: 50GR; Approvals: UL,CSA
R647 = Resistor: Manufacturer 1: Panasonic; Manufacturer Part Number 1: ERA-2AED104X; Tolerance: 0.5%; Power Rating: 63mW; Voltage Rating: 25V; Temperature Coefficient: 25ppm/°C
R648 = Resistor: Manufacturer 1: Yageo; Manufacturer Part Number 1: RC0402FR-072RL; Power Rating: 63mW; Tolerance: 1%; Voltage Rating: 50V; Temperature Coefficient: 200ppm/°C
R649 R651 R655 R656 R658 = Resistor: SMT Resistor
R650 = Resistor: RES SMD 100M OHM 5% 1/16W 0402; Manufacturer: Stackpole Electronics; Manufacturer Part Number: HMC0402JT100M; Max Power Dissipation: 63mW; Temperature Coefficient: 400ppm/°C
R652 = Resistor: RES SMD 1M OHM 1% 1/16W 0402; Manufacturer: Yageo; Manufacturer Part Number: RC0402FR-071ML; Power Rating: 63mW; Voltage Rating: 50V; Temperature Coefficient: 100ppm/°C
R653 = Resistor: RES SMD 20 OHM 5% 1/5W 0402; Manufacturer: Rohm; Manufacturer Part Number: ESR01MZPJ200; Max Power Dissipation: 200mW; Temperature Coefficient: 200ppm/°C
R654 R657 = Resistor: RES SMD 100 OHM 1% 1/16W 0402; Manufacturer: Yageo; Manufacturer Part Number: RC0402FR-07100RL; Power Rating: 62.5mW; Voltage Rating: 50V; Temperature Coefficient: 100ppm/°C
T22 T23 T27 T30 = IRLML6401TRPBF: MOSFET MOSFT P-Ch -4.3A 50mOhm 10nC Log Lvl; Manufacturer: International Rectifier; Nominal Vgs: -550mV; Rds On Max: 50mR; Input Capacitance: 830pF; Rise Time: 32ns; Max Power Dissipation: 1.3W; Number of Elements: 1; Dual Supply Voltage: -12V; Drain to Source Voltage (Vdss): 12V; Continuous Drain Current (ID): 4.3A; Gate to Source Voltage (Vgs): 8V; Turn-On Delay Time: 11ns; Turn-Off Delay Time: 250ns; Fall Time: 210ns; Element Configuration: Single
T24-T26 T28 T29 T31 = SI2342DS-T1-GE3: Trans MOSFET N-CH 8V 6A 3-Pin SOT-23 T/R; Manufacturer: Vishay; Rds On Max: 17mR; Input Capacitance: 1.07nF; Rise Time: 14ns; Max Power Dissipation: 2.5W; Number of Elements: 1; Power Dissipation: 1.3W; Turn-On Delay Time: 6ns; Turn-Off Delay Time: 65ns; Fall Time: 25ns; Threshold Voltage: 800mV; Gate to Source Voltage (Vgs): 5V

## Sheet Peripherals.SchDoc
size A3
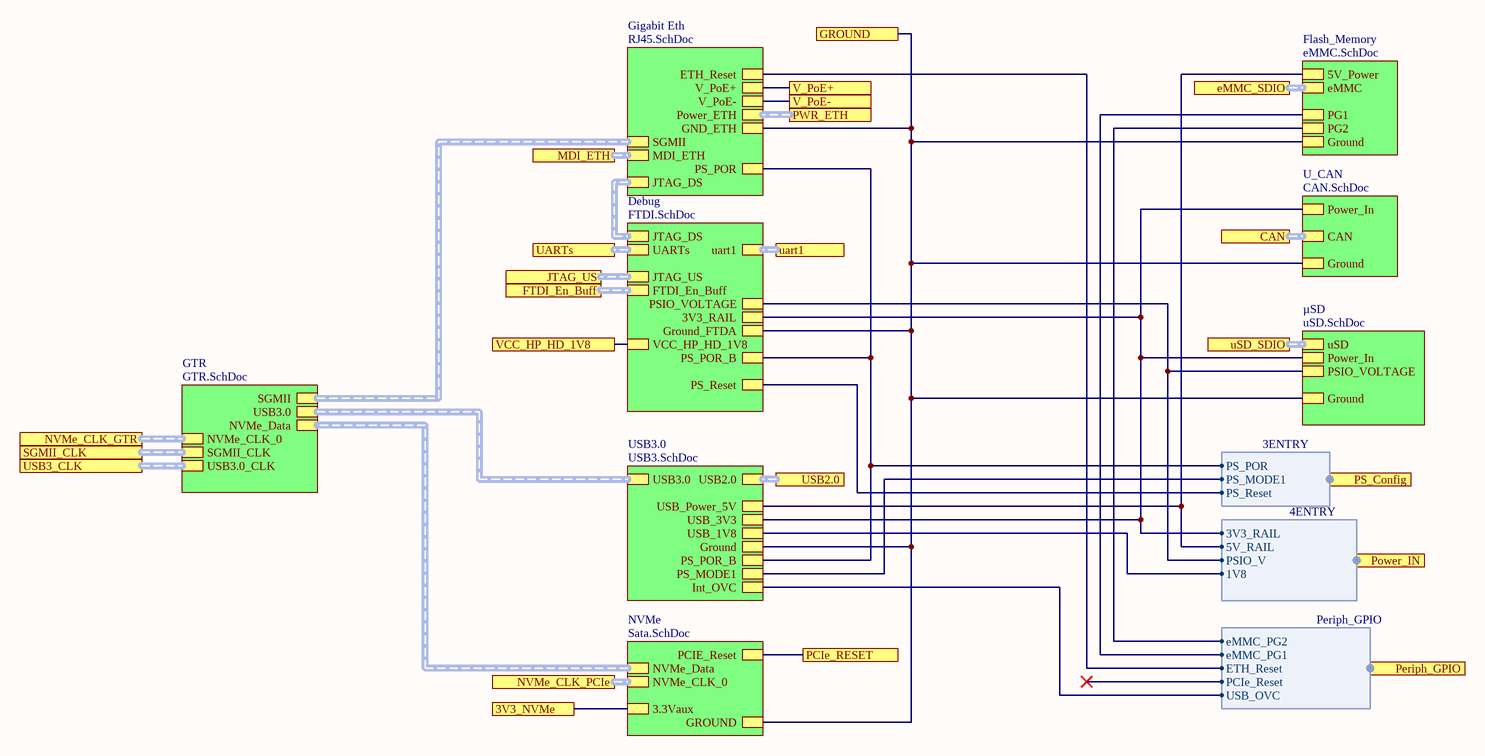
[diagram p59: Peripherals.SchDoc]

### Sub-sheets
Debug = FTDI.SchDoc: uart1 (harness uart), UARTs (harness 2Uarts), JTAG_US (harness JTAG), JTAG_DS (harness JTAG), PSIO_VOLTAGE, PS_POR_B, PS_Reset, 3V3_RAIL, Ground_FTDA, VCC_HP_HD_1V8, FTDI_En_Buff (harness FTDI_En_Buff)
Flash_Memory = eMMC.SchDoc: 5V_Power, Ground, eMMC (harness SDIO_H), PG2, PG1
Gigabit Eth = RJ45.SchDoc: JTAG_DS (harness JTAG), SGMII (harness Diff_2PairData), V_PoE-, V_PoE+, Power_ETH (harness Power_ETH), MDI_ETH (harness MDI_ETH), PS_POR, ETH_Reset, GND_ETH
GTR = GTR.SchDoc: USB3.0 (harness Diff_2PairData), NVMe_Data (harness NVMe_Data), SGMII (harness Diff_2PairData), SGMII_CLK (harness Diff_1Pair), USB3.0_CLK (harness Diff_1Pair), NVMe_CLK_0 (harness Diff_1Pair)
NVMe = Sata.SchDoc: NVMe_CLK_0 (harness Diff_1Pair), NVMe_Data (harness NVMe_Data), GROUND, 3.3Vaux, PCIE_Reset
U_CAN = CAN.SchDoc: Power_In, Ground, CAN (harness CAN)
USB3.0 = USB3.SchDoc: USB3.0 (harness Diff_2PairData), USB2.0 (harness USB_H), USB_1V8, USB_Power_5V, Ground, USB_3V3, PS_MODE1, PS_POR_B, Int_OVC
µSD = uSD.SchDoc: uSD (harness SDIO_H), Ground, Power_In, PSIO_VOLTAGE

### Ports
3V3_NVMe, CAN (harness CAN), eMMC_SDIO (harness SDIO_H), FTDI_En_Buff (harness FTDI_En_Buff), GROUND, JTAG_US (harness JTAG), MDI_ETH (harness MDI_ETH), NVMe_CLK_GTR (harness Diff_1Pair), NVMe_CLK_PCIe (harness Diff_1Pair), PCIe_RESET, Periph_GPIO (harness Periph_GPIO), Power_IN (harness 4ENTRY), PS_Config (harness 3ENTRY), PWR_ETH (harness Power_ETH), SGMII_CLK (harness Diff_1Pair), uart1 (harness uart), UARTs (harness 2Uarts), USB2.0 (harness USB_H), USB3_CLK (harness Diff_1Pair), uSD_SDIO (harness SDIO_H), V_PoE+, V_PoE-, VCC_HP_HD_1V8

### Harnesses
4ENTRY: 3V3_RAIL, 5V_RAIL, PSIO_V, 1V8
3ENTRY: PS_POR, PS_MODE1, PS_Reset
Periph_GPIO: eMMC_PG2, eMMC_PG1, ETH_Reset, PCIe_Reset, USB_OVC

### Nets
B503_Ground: port GROUND, sheet Gigabit Eth/GND_ETH, sheet NVMe/GROUND, sheet µSD/Ground, sheet Debug/Ground_FTDA, sheet USB3.0/Ground, sheet U_CAN/Ground, sheet Flash_Memory/Ground
1V8@1.5A: sheet USB3.0/USB_1V8, port Power_IN.1V8
3V3_NVMe: port 3V3_NVMe, sheet NVMe/3.3Vaux
3V3_RAIL: sheet µSD/Power_In, sheet Debug/3V3_RAIL, sheet USB3.0/USB_3V3, sheet U_CAN/Power_In, port Power_IN.3V3_RAIL
5V_RAIL: sheet USB3.0/USB_Power_5V, sheet Flash_Memory/5V_Power, port Power_IN.5V_RAIL
eMMC_PG1: sheet Flash_Memory/PG1, port Periph_GPIO.eMMC_PG1
eMMC_PG2: sheet Flash_Memory/PG2, port Periph_GPIO.eMMC_PG2
ETH_VDDIO: sheet µSD/PSIO_VOLTAGE, sheet Debug/PSIO_VOLTAGE, port Power_IN.PSIO_V
GPIO_ETH_EXPANDER: sheet Gigabit Eth/ETH_Reset, port Periph_GPIO.ETH_Reset
GPIOa_01.GPIO5: sheet USB3.0/Int_OVC, port Periph_GPIO.USB_OVC
PCIe_RESET: port PCIe_RESET, sheet NVMe/PCIE_Reset
PGND: port V_PoE-, sheet Gigabit Eth/V_PoE-
PS_MODE1: sheet USB3.0/PS_MODE1, port PS_Config.PS_MODE1
PS_POR: sheet Gigabit Eth/PS_POR, sheet Debug/PS_POR_B, sheet USB3.0/PS_POR_B, port PS_Config.PS_POR
PS_Reset: sheet Debug/PS_Reset, port PS_Config.PS_Reset
US+_MGTVccAux: port VCC_HP_HD_1V8, sheet Debug/VCC_HP_HD_1V8
V_PoE+: port V_PoE+, sheet Gigabit Eth/V_PoE+

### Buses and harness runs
harness port CAN = sheet U_CAN/CAN
harness port eMMC_SDIO = sheet Flash_Memory/eMMC
harness port FTDI_En_Buff = sheet Debug/FTDI_En_Buff
harness port JTAG_US = sheet Debug/JTAG_US
harness port MDI_ETH = sheet Gigabit Eth/MDI_ETH
harness port NVMe_CLK_GTR = sheet GTR/NVMe_CLK_0
harness port NVMe_CLK_PCIe = sheet NVMe/NVMe_CLK_0
harness port PWR_ETH = sheet Gigabit Eth/Power_ETH
harness port SGMII_CLK = sheet GTR/SGMII_CLK
harness port uart1 = sheet Debug/uart1
harness port UARTs = sheet Debug/UARTs
harness port USB2.0 = sheet USB3.0/USB2.0
harness port USB3_CLK = sheet GTR/USB3.0_CLK
harness port uSD_SDIO = sheet µSD/uSD
harness sheet Debug/JTAG_DS = sheet Gigabit Eth/JTAG_DS
harness sheet Gigabit Eth/SGMII = sheet GTR/SGMII
harness sheet GTR/NVMe_Data = sheet NVMe/NVMe_Data
harness sheet GTR/USB3.0 = sheet USB3.0/USB3.0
